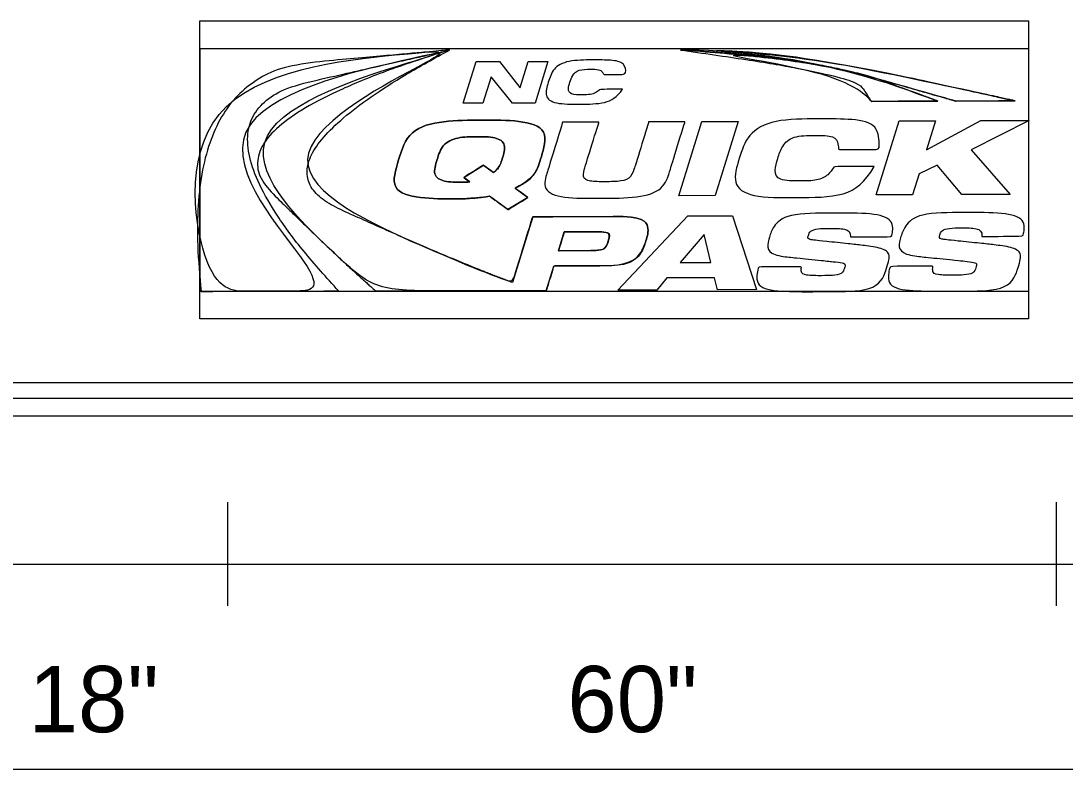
# Model space of a CAD drawing. Extents: x 10268259 to 10268554, y 2141099 to 2141249.
# Drawn here: x 10268367.06 to 10268378.4, y 2141173.53 to 2141181.66 of the extents above; entities that cross this region are included whole.
import ezdxf

# ---------------------------------------------------------------- set-up
doc = ezdxf.new("R2010")
doc.units = 0
for name, color, linetype in [('60', 7, 'Continuous'), ('Default', 7, 'Continuous'), ('GSColorFill', 7, 'Continuous'), ('GSDims', 7, 'Continuous'), ('GSSign', 7, 'Continuous'), ('Level 54', 7, 'Continuous')]:
    doc.layers.add(name, color=color, linetype=linetype)

# ---------------------------------------------------------------- blocks, each defined once
blk = doc.blocks.new('block 2')
at = {"layer": 'Default'}
for p, q in [((994.2, 462.7), (1036.5, 598)), ((1036.5, 598), (1102.9, 598)), ((1102.9, 598), (1060.6, 462.7)), ((1355.1, 462.7), (1397.4, 598)), ((1397.4, 598), (1463.8, 598)), ((1463.8, 598), (1447.2, 544.9)), ((1447.2, 544.9), (1546.9, 598)), ((1635.3, 598), (1528.6, 544.8)), ((1546.9, 598), (1635.3, 598)), ((1528.6, 544.8), (1600.1, 462.7)), ((1466.6, 516.7), (1433.4, 500.8)), ((1511.3, 462.7), (1466.6, 516.7)), ((1433.4, 500.8), (1421.5, 462.7)), ((1060.6, 462.7), (994.2, 462.7)), ((1421.5, 462.7), (1355.1, 462.7)), ((1600.1, 462.7), (1511.3, 462.7))]:
    blk.add_line(p, q, dxfattribs=at)
for points in [[(1036.5, 598), (1102.9, 598), (1060.6, 462.7), (994.2, 462.7), (1036.5, 598)], [(1397.4, 598), (1463.8, 598), (1447.2, 544.9), (1546.9, 598), (1635.3, 598), (1528.6, 544.8), (1600.1, 462.7), (1511.3, 462.7), (1466.6, 516.7), (1433.4, 500.8), (1421.5, 462.7), (1355.1, 462.7), (1397.4, 598)], [(612.1, 489.4), (600.9, 497.6), (636.9, 519.7), (655.3, 506.3)], [(694.6, 477.7), (717.7, 460.4), (681.5, 438.4), (648.1, 462.9)]]:
    blk.add_lwpolyline(points, dxfattribs=at)
for points in [[(648.1, 462.9), (638.5, 461.4), (628.7, 460.4), (619, 459.7), (609, 458.9), (599.4, 458.5), (589.3, 458.5), (519, 458.5), (464.5, 474.2), (482, 530.3), (499.6, 586.4), (563.9, 602.2), (634.2, 602.2), (704.5, 602.2), (759, 586.4), (741.5, 530.3), (733.7, 505.5), (716.7, 488.7), (694.6, 477.7), (694.6, 477.7), (717.7, 460.4), (717.7, 460.4), (717.7, 460.4), (681.5, 438.4), (681.5, 438.4), (681.5, 438.4), (648.1, 462.9), (648.1, 462.9)], [(648.1, 462.9), (638.5, 461.4), (628.7, 460.4), (619, 459.7), (609, 458.9), (599.4, 458.5), (589.3, 458.5), (519, 458.5), (464.5, 474.2), (482, 530.3), (499.6, 586.4), (563.9, 602.2), (634.2, 602.2), (704.5, 602.2), (759, 586.4), (741.5, 530.3), (733.7, 505.5), (716.7, 488.7), (694.6, 477.7)], [(782.1, 598), (782.1, 598), (848.5, 598), (848.5, 598), (848.5, 598), (823.4, 517.8), (823.4, 517.8), (816.6, 495.9), (829.5, 488.8), (859.9, 488.8), (890.3, 488.8), (907.5, 495.9), (914.4, 517.8), (914.4, 517.8), (939.4, 598), (939.4, 598), (939.4, 598), (1005.8, 598), (1005.8, 598), (1005.8, 598), (978.5, 510.4), (978.5, 510.4), (966.8, 473.1), (921, 458.5), (850.4, 458.5), (779.8, 458.5), (743.1, 473.1), (754.7, 510.4), (754.7, 510.4), (782.1, 598), (782.1, 598)], [(782.1, 598), (782.1, 598), (848.5, 598), (848.5, 598), (848.5, 598), (823.4, 517.8), (823.4, 517.8), (816.6, 495.9), (829.5, 488.8), (859.9, 488.8), (890.3, 488.8), (907.5, 495.9), (914.4, 517.8), (914.4, 517.8), (939.4, 598), (939.4, 598), (939.4, 598), (1005.8, 598), (1005.8, 598), (1005.8, 598), (978.5, 510.4), (978.5, 510.4), (966.8, 473.1), (921, 458.5), (850.4, 458.5), (779.8, 458.5), (743.1, 473.1), (754.7, 510.4), (754.7, 510.4), (782.1, 598), (782.1, 598)], [(1351.4, 514.8), (1334.1, 485.6), (1302, 458.5), (1207.7, 458.5), (1123.4, 458.5), (1090.3, 483.7), (1104.9, 530.3), (1119, 575.6), (1166.1, 602.2), (1252.6, 602.2), (1313.4, 602.2), (1360.6, 592.7), (1360.5, 545.9), (1360.5, 545.9), (1286.6, 545.9), (1286.6, 545.9), (1285.7, 555.6), (1281, 571.9), (1243.4, 571.9), (1201.8, 571.9), (1182.2, 552.7), (1175.2, 530.3), (1168.2, 508), (1174.5, 488.8), (1217.4, 488.8), (1247.3, 488.8), (1268.3, 499.1), (1277.7, 514.8), (1277.7, 514.8), (1351.4, 514.8), (1351.4, 514.8)], [(1351.4, 514.8), (1334.1, 485.6), (1302, 458.5), (1207.7, 458.5), (1123.4, 458.5), (1090.3, 483.7), (1104.9, 530.3), (1119, 575.6), (1166.1, 602.2), (1252.6, 602.2), (1313.4, 602.2), (1360.6, 592.7), (1360.5, 545.9), (1360.5, 545.9), (1286.6, 545.9), (1286.6, 545.9), (1285.7, 555.6), (1281, 571.9), (1243.4, 571.9), (1201.8, 571.9), (1182.2, 552.7), (1175.2, 530.3), (1168.2, 508), (1174.5, 488.8), (1217.4, 488.8), (1247.3, 488.8), (1268.3, 499.1), (1277.7, 514.8), (1277.7, 514.8), (1351.4, 514.8), (1351.4, 514.8)], [(600.9, 497.6), (600.9, 497.6), (636.9, 519.7), (636.9, 519.7), (636.9, 519.7), (655.3, 506.3), (655.3, 506.3), (662.8, 512.3), (668.1, 520.5), (671.2, 530.3), (680, 558.6), (660.4, 571.9), (624.7, 571.9), (589.3, 571.9), (561.1, 558.6), (552.3, 530.3), (543.4, 501.9), (563.4, 488.8), (598.8, 488.8), (603.3, 488.8), (607.2, 489), (612.1, 489.4), (612.1, 489.4), (600.9, 497.6), (600.9, 497.6)], [(655.3, 506.3), (662.8, 512.3), (668.1, 520.5), (671.2, 530.3), (680, 558.6), (660.4, 571.9), (624.7, 571.9), (589.3, 571.9), (561.1, 558.6), (552.3, 530.3), (543.4, 501.9), (563.4, 488.8), (598.8, 488.8), (603.3, 488.8), (607.2, 489), (612.1, 489.4)]]:
    blk.add_open_spline(points, degree=3, dxfattribs=at)
blk = doc.blocks.new('block 5')
at = {"layer": 'Default'}
for p, q in [((600.6, 633.1), (624.3, 709.2)), ((624.3, 709.2), (667.3, 709.2)), ((667.3, 709.2), (704.3, 661.6)), ((704.6, 661.6), (719.5, 709.2)), ((719.5, 709.2), (755.6, 709.2)), ((755.6, 709.2), (731.8, 633.1)), ((651.6, 681.2), (636.6, 633.1)), ((652, 681.2), (651.6, 681.2)), ((690.6, 633.1), (652, 681.2)), ((704.3, 661.6), (704.6, 661.6)), ((636.6, 633.1), (600.6, 633.1)), ((731.8, 633.1), (690.6, 633.1))]:
    blk.add_line(p, q, dxfattribs=at)
blk.add_lwpolyline([(624.3, 709.2), (667.3, 709.2), (704.3, 661.6), (704.6, 661.6), (719.5, 709.2), (755.6, 709.2), (731.8, 633.1), (690.6, 633.1), (652, 681.2), (651.6, 681.2), (636.6, 633.1), (600.6, 633.1), (624.3, 709.2)], dxfattribs=at)
blk.add_open_spline([(891.7, 657.7), (881.3, 643.2), (861.9, 630.8), (814, 630.8), (766.7, 630.8), (748, 644.9), (756.2, 671.1), (764.2, 696.6), (790.6, 711.5), (839.3, 711.5), (871.3, 711.5), (896.6, 706.9), (899.6, 684.7), (889.7, 684.7), (860.4, 684.7), (857.3, 684.7), (855.3, 689.5), (849.7, 694.5), (834.1, 694.5), (810.7, 694.5), (799.7, 683.7), (795.7, 671.1), (791.8, 658.6), (795.3, 647.8), (819.5, 647.8), (833.1, 647.8), (843.4, 651.6), (849.6, 657.7), (858.2, 657.7), (887, 657.7), (891.7, 657.7)], degree=3, dxfattribs=at)
blk.add_open_spline([(891.7, 657.7), (881.3, 643.2), (861.9, 630.8), (814, 630.8), (766.7, 630.8), (748, 644.9), (756.2, 671.1), (764.2, 696.6), (790.6, 711.5), (839.3, 711.5), (871.3, 711.5), (896.6, 706.9), (899.6, 684.7), (889.7, 684.7), (860.4, 684.7), (857.3, 684.7), (855.3, 689.5), (849.7, 694.5), (834.1, 694.5), (810.7, 694.5), (799.7, 683.7), (795.7, 671.1), (791.8, 658.6), (795.3, 647.8), (819.5, 647.8), (833.1, 647.8), (843.4, 651.6), (849.6, 657.7), (858.2, 657.7), (887, 657.7), (891.7, 657.7)], degree=3, dxfattribs=at)
blk = doc.blocks.new('block 4')
at = {"layer": 'Default'}
for p, q in [((1346.7, 633.7), (1468.3, 633.9)), ((1500.7, 633.7), (1609.8, 633.7)), ((881.8, 290.4), (1010.5, 425.8)), ((1010.5, 425.8), (1091.7, 425.8)), ((1091.7, 425.8), (1135.1, 290.4)), ((1039.8, 391.6), (996.1, 340.5)), ((1040.3, 391.6), (1039.8, 391.6)), ((1051.9, 340.5), (1040.3, 391.6)), ((996.1, 340.5), (1051.9, 340.5)), ((971.8, 312.4), (952.9, 290.4)), ((1058.8, 312.4), (971.8, 312.4)), ((1063.9, 290.4), (1058.8, 312.4)), ((952.9, 290.4), (881.8, 290.4)), ((1135.1, 290.4), (1063.9, 290.4))]:
    blk.add_line(p, q, dxfattribs=at)
for points in [[(874.1, 425.2), (726.8, 425.2), (689.2, 304.9)], [(1010.5, 425.8), (1091.7, 425.8), (1135.1, 290.4), (1063.9, 290.4), (1058.8, 312.4), (971.8, 312.4), (952.9, 290.4), (881.8, 290.4), (1010.5, 425.8)], [(832.9, 363), (773.8, 363), (784.4, 397.2), (843.6, 397.2)], [(1040.3, 391.6), (1039.8, 391.6), (996.1, 340.5), (1051.9, 340.5), (1040.3, 391.6)], [(750.9, 289.9), (765, 335), (849, 335)]]:
    blk.add_lwpolyline(points, dxfattribs=at)
for points, degree in [([(874.1, 425.2), (874.1, 425.2), (726.8, 425.2), (726.8, 425.2), (726.8, 425.2), (689.2, 304.9), (689.2, 304.9), (558.5, 355.1), (189.6, 525.7), (575.7, 730.8), (575.7, 730.8), (76.7, 687.3), (120.1, 291), (206.3, 291), (292.2, 291), (371.2, 290.8), (68.8, 617.9), (571.4, 729.5), (571.4, 729.5), (126.6, 593.3), (376.1, 345.7), (439.2, 290.7), (545.6, 290.5), (750.9, 289.9), (750.9, 289.9), (750.9, 289.9), (765, 335), (765, 335), (765, 335), (849, 335), (849, 335), (902.6, 335), (926.4, 357.7), (933.4, 380.1), (941.4, 405.7), (928.2, 425.2), (874.1, 425.2)], 3), ([(575.7, 730.8), (575.7, 730.8), (76.7, 687.3), (120.1, 291)], 2), ([(371.2, 290.8), (68.8, 617.9), (571.4, 729.5), (571.4, 729.5)], 2), ([(571.4, 729.5), (126.6, 593.3), (376.1, 345.7), (439.2, 290.7)], 2), ([(689.2, 304.9), (558.5, 355.1), (189.6, 525.7), (575.7, 730.8)], 2), ([(1609.8, 633.7), (1609.8, 633.7), (1605.3, 634.8), (1597, 636.7), (1526.5, 652.5), (1182.8, 727.9), (997.9, 729)], 3), ([(997.9, 729), (1207.7, 719.3), (1486.2, 638), (1500.7, 633.7)], 2), ([(997.9, 729), (1313.6, 684.8), (1346.7, 633.7), (1346.7, 633.7)], 2), ([(1468.3, 633.9), (1468.3, 633.9), (1267.7, 708.5), (997.9, 729)], 2), ([(1609.8, 633.7), (1609.8, 633.7), (1605.3, 634.8), (1597, 636.7), (1526.5, 652.5), (1182.8, 727.9), (997.9, 729), (1207.7, 719.3), (1486.2, 638), (1500.7, 633.7), (1500.7, 633.7), (1609.8, 633.7), (1609.8, 633.7)], 3), ([(1346.7, 633.7), (1346.7, 633.7), (1468.3, 633.9), (1468.3, 633.9), (1468.3, 633.9), (1267.7, 708.5), (997.9, 729), (1313.6, 684.8), (1346.7, 633.7), (1346.7, 633.7)], 3), ([(849, 335), (902.6, 335), (926.4, 357.7), (933.4, 380.1), (941.4, 405.7), (928.2, 425.2), (874.1, 425.2)], 3), ([(1307.5, 386.2), (1308.4, 395.4), (1299.6, 401.9), (1269.1, 401.9), (1246.8, 401.9), (1233.2, 397.5), (1230.4, 388.6), (1229, 384.1), (1232.9, 381.4), (1242.6, 380.3), (1258.7, 378.4), (1308.2, 373.3), (1327, 371), (1362.7, 366.6), (1381.9, 356.4), (1374.4, 332.5), (1360.1, 286.7), (1272.4, 286.3), (1245, 286.3), (1177.5, 286.3), (1131.3, 294.4), (1139.1, 332.1), (1139.1, 332.1), (1217.8, 332.1), (1217.8, 332.1), (1216.3, 321.9), (1222.6, 315.5), (1257.2, 315.5), (1274, 315.5), (1292.9, 318.1), (1296.5, 329.7), (1298.8, 336.9), (1291.2, 339.3), (1268.8, 341.8), (1268.8, 341.8), (1204.5, 348.6), (1204.5, 348.6), (1164.8, 352.8), (1153.3, 366.8), (1159.6, 386.9), (1165.1, 404.7), (1189.2, 429.9), (1276.5, 429.9), (1348.8, 429.9), (1388.6, 418.2), (1382.8, 386.2), (1382.8, 386.2), (1307.5, 386.2), (1307.5, 386.2)], 3), ([(1307.5, 386.2), (1308.4, 395.4), (1299.6, 401.9), (1269.1, 401.9), (1246.8, 401.9), (1233.2, 397.5), (1230.4, 388.6), (1229, 384.1), (1232.9, 381.4), (1242.6, 380.3), (1258.7, 378.4), (1308.2, 373.3), (1327, 371), (1362.7, 366.6), (1381.9, 356.4), (1374.4, 332.5), (1360.1, 286.7), (1272.4, 286.3), (1245, 286.3), (1177.5, 286.3), (1131.3, 294.4), (1139.1, 332.1), (1139.1, 332.1), (1217.8, 332.1), (1217.8, 332.1), (1216.3, 321.9), (1222.6, 315.5), (1257.2, 315.5), (1274, 315.5), (1292.9, 318.1), (1296.5, 329.7), (1298.8, 336.9), (1291.2, 339.3), (1268.8, 341.8), (1268.8, 341.8), (1204.5, 348.6), (1204.5, 348.6), (1164.8, 352.8), (1153.3, 366.8), (1159.6, 386.9), (1165.1, 404.7), (1189.2, 429.9), (1276.5, 429.9), (1348.8, 429.9), (1388.6, 418.2), (1382.8, 386.2), (1382.8, 386.2), (1307.5, 386.2), (1307.5, 386.2)], 3), ([(1547.9, 386.2), (1548.8, 395.4), (1540, 401.9), (1509.6, 401.9), (1487.2, 401.9), (1473.6, 397.5), (1470.8, 388.6), (1469.4, 384.1), (1473.3, 381.4), (1483, 380.3), (1499.1, 378.4), (1548.6, 373.3), (1567.4, 371), (1603.2, 366.6), (1622.3, 356.4), (1614.8, 332.5), (1600.5, 286.7), (1512.8, 286.3), (1485.4, 286.3), (1417.9, 286.3), (1371.7, 294.4), (1379.5, 332.1), (1379.5, 332.1), (1458.2, 332.1), (1458.2, 332.1), (1456.7, 321.9), (1463, 315.5), (1497.6, 315.5), (1514.4, 315.5), (1533.3, 318.1), (1536.9, 329.7), (1539.2, 336.9), (1531.6, 339.3), (1509.2, 341.8), (1509.2, 341.8), (1444.9, 348.6), (1444.9, 348.6), (1405.3, 352.8), (1393.7, 366.8), (1400, 386.9), (1405.6, 404.7), (1429.6, 429.9), (1516.9, 429.9), (1589.2, 429.9), (1629, 418.2), (1623.2, 386.2), (1623.2, 386.2), (1547.9, 386.2), (1547.9, 386.2)], 3), ([(1547.9, 386.2), (1548.8, 395.4), (1540, 401.9), (1509.6, 401.9), (1487.2, 401.9), (1473.6, 397.5), (1470.8, 388.6), (1469.4, 384.1), (1473.3, 381.4), (1483, 380.3), (1499.1, 378.4), (1548.6, 373.3), (1567.4, 371), (1603.2, 366.6), (1622.3, 356.4), (1614.8, 332.5), (1600.5, 286.7), (1512.8, 286.3), (1485.4, 286.3), (1417.9, 286.3), (1371.7, 294.4), (1379.5, 332.1), (1379.5, 332.1), (1458.2, 332.1), (1458.2, 332.1), (1456.7, 321.9), (1463, 315.5), (1497.6, 315.5), (1514.4, 315.5), (1533.3, 318.1), (1536.9, 329.7), (1539.2, 336.9), (1531.6, 339.3), (1509.2, 341.8), (1509.2, 341.8), (1444.9, 348.6), (1444.9, 348.6), (1405.3, 352.8), (1393.7, 366.8), (1400, 386.9), (1405.6, 404.7), (1429.6, 429.9), (1516.9, 429.9), (1589.2, 429.9), (1629, 418.2), (1623.2, 386.2), (1623.2, 386.2), (1547.9, 386.2), (1547.9, 386.2)], 3), ([(864.8, 380.1), (861, 368.2), (851.3, 363), (832.9, 363), (832.9, 363), (773.8, 363), (773.8, 363), (773.8, 363), (784.4, 397.2), (784.4, 397.2), (784.4, 397.2), (843.6, 397.2), (843.6, 397.2), (862, 397.2), (868.5, 392.1), (864.8, 380.1)], 3), ([(843.6, 397.2), (862, 397.2), (868.5, 392.1), (864.8, 380.1)], 2), ([(864.8, 380.1), (861, 368.2), (851.3, 363), (832.9, 363)], 2), ([(120.1, 291), (206.3, 291), (292.2, 291), (371.2, 290.8)], 2), ([(439.2, 290.7), (545.6, 290.5), (750.9, 289.9), (750.9, 289.9)], 2)]:
    blk.add_open_spline(points, degree=degree, dxfattribs=at)
blk.add_blockref('block 5', (0, 0), dxfattribs=at)
blk = doc.blocks.new('block 3_1')
at = {"layer": 'Default'}
blk.add_blockref('block 4', (0, 0), dxfattribs=at)

msp = doc.modelspace()

# ---------------------------------------------------------------- linework, layer by layer
at = {"layer": '60'}
msp.add_line((10268341.73, 2141173.528), (10268393.98, 2141173.528), dxfattribs=at)
at = {"layer": 'GSColorFill'}
msp.add_line((10268356.249, 2141177.728), (10268379.649, 2141177.728), dxfattribs=at)
at = {"layer": 'GSDims'}
for p, q in [((10268369.299, 2141176.428), (10268369.299, 2141175.303)), ((10268378.299, 2141176.428), (10268378.299, 2141175.303)), ((10268366.599, 2141175.753), (10268369.299, 2141175.753)), ((10268369.299, 2141175.753), (10268378.299, 2141175.753)), ((10268378.299, 2141175.753), (10268381.449, 2141175.753))]:
    msp.add_line(p, q, dxfattribs=at)
at = {"layer": 'GSSign'}
for p, q in [((10268368.999, 2141181.355), (10268377.999, 2141181.355)), ((10268368.999, 2141181.355), (10268368.999, 2141178.718)), ((10268377.999, 2141181.355), (10268377.999, 2141178.718)), ((10268368.999, 2141178.718), (10268377.999, 2141178.718))]:
    msp.add_line(p, q, dxfattribs=at)
msp.add_lwpolyline([(10268368.999, 2141181.655), (10268377.999, 2141181.655), (10268377.999, 2141178.418), (10268368.999, 2141178.418)], close=True, dxfattribs=at)
at = {"layer": 'Level 54'}
for p, q in [((10268379.649, 2141177.555), (10268356.251, 2141177.555)), ((10268356.251, 2141177.367), (10268379.649, 2141177.367))]:
    msp.add_line(p, q, dxfattribs=at)

# ---------------------------------------------------------------- block references
at = {"layer": 'Default', "xscale": 0.005939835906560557, "yscale": 0.005939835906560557, "rotation": 0.21377925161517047}
for name in ['block 3_1', 'block 2']:
    msp.add_blockref(name, (10268368.308, 2141176.986), dxfattribs=at)

# ---------------------------------------------------------------- texts
at = {"layer": 'GSDims'}
for s, p in [('18"', (10268367.142, 2141173.929)), ('60"', (10268372.992, 2141173.929))]:
    msp.add_text(s, height=0.72, dxfattribs=at).set_placement(p)

doc.saveas('drawing.dxf')
